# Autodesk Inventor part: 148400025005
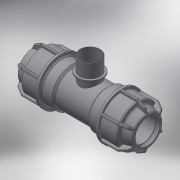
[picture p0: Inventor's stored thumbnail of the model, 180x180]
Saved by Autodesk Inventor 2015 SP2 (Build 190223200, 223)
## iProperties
Created: 2017-08
Part Number: 148400025005
Material: Generic
Description: PLASSON L.14 TEE MALE ADAPTOR (SILVER) 25-1/2"-25
Document SubType Name: Modeling
Designer: KIM
Density: 1 g/cm^3
Appearance: Default
Author: KIM
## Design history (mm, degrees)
derived "148400.ipt"
feature "Solid1::148400.ipt"
feature "Solid2::148400.ipt"
tag "TaggingFeature1"
body "Solid1"
body "Solid2"
other parameters: "d1" = 25, "d2" = 48, "d4" = 15 deg, "d5" = 31.68, "d6" = 10.4544, "d16" = 25.5, "d17" = 2.4, "d24" = 2.4, "d25" = 45, "d26" = 37.5, "d27" = 2.4, "d28" = 135 deg, "d29" = 1.44, "d31" = 1.25, "d46" = 150 deg, "d49" = 2.5, "d50" = 0, "d58" = 0.75, "d61" = 360 deg, "d63" = 22.5, "d64" = 62, "d80" = 36, "d81" = 2, "d84" = 2.4, "d94" = 45, "d96" = 20.955, "d108" = 0.75, "d111" = 0, "d113" = 15, "d114" = 25.146, "d115" = 17, "d116" = 1.7, "d117" = 20.955, "d_" = 25, "R_" = 20.955, "H_" = 124, "l_" = 48, "l_2" = 17, "A_" = 45
